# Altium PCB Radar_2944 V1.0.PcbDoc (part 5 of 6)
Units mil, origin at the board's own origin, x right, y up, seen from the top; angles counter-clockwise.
Board outline 3544.83 x 2556.65 mil, 8 copper layers (Top Layer, GND1, SIG1, PWR1, PWR2, SIG2, GND2, Bottom Layer), stack 55.2 mil thick; 301 components, 253 nets, 1055 pads, 1340 vias.
Unrouted connection lines stored in the file: 12.
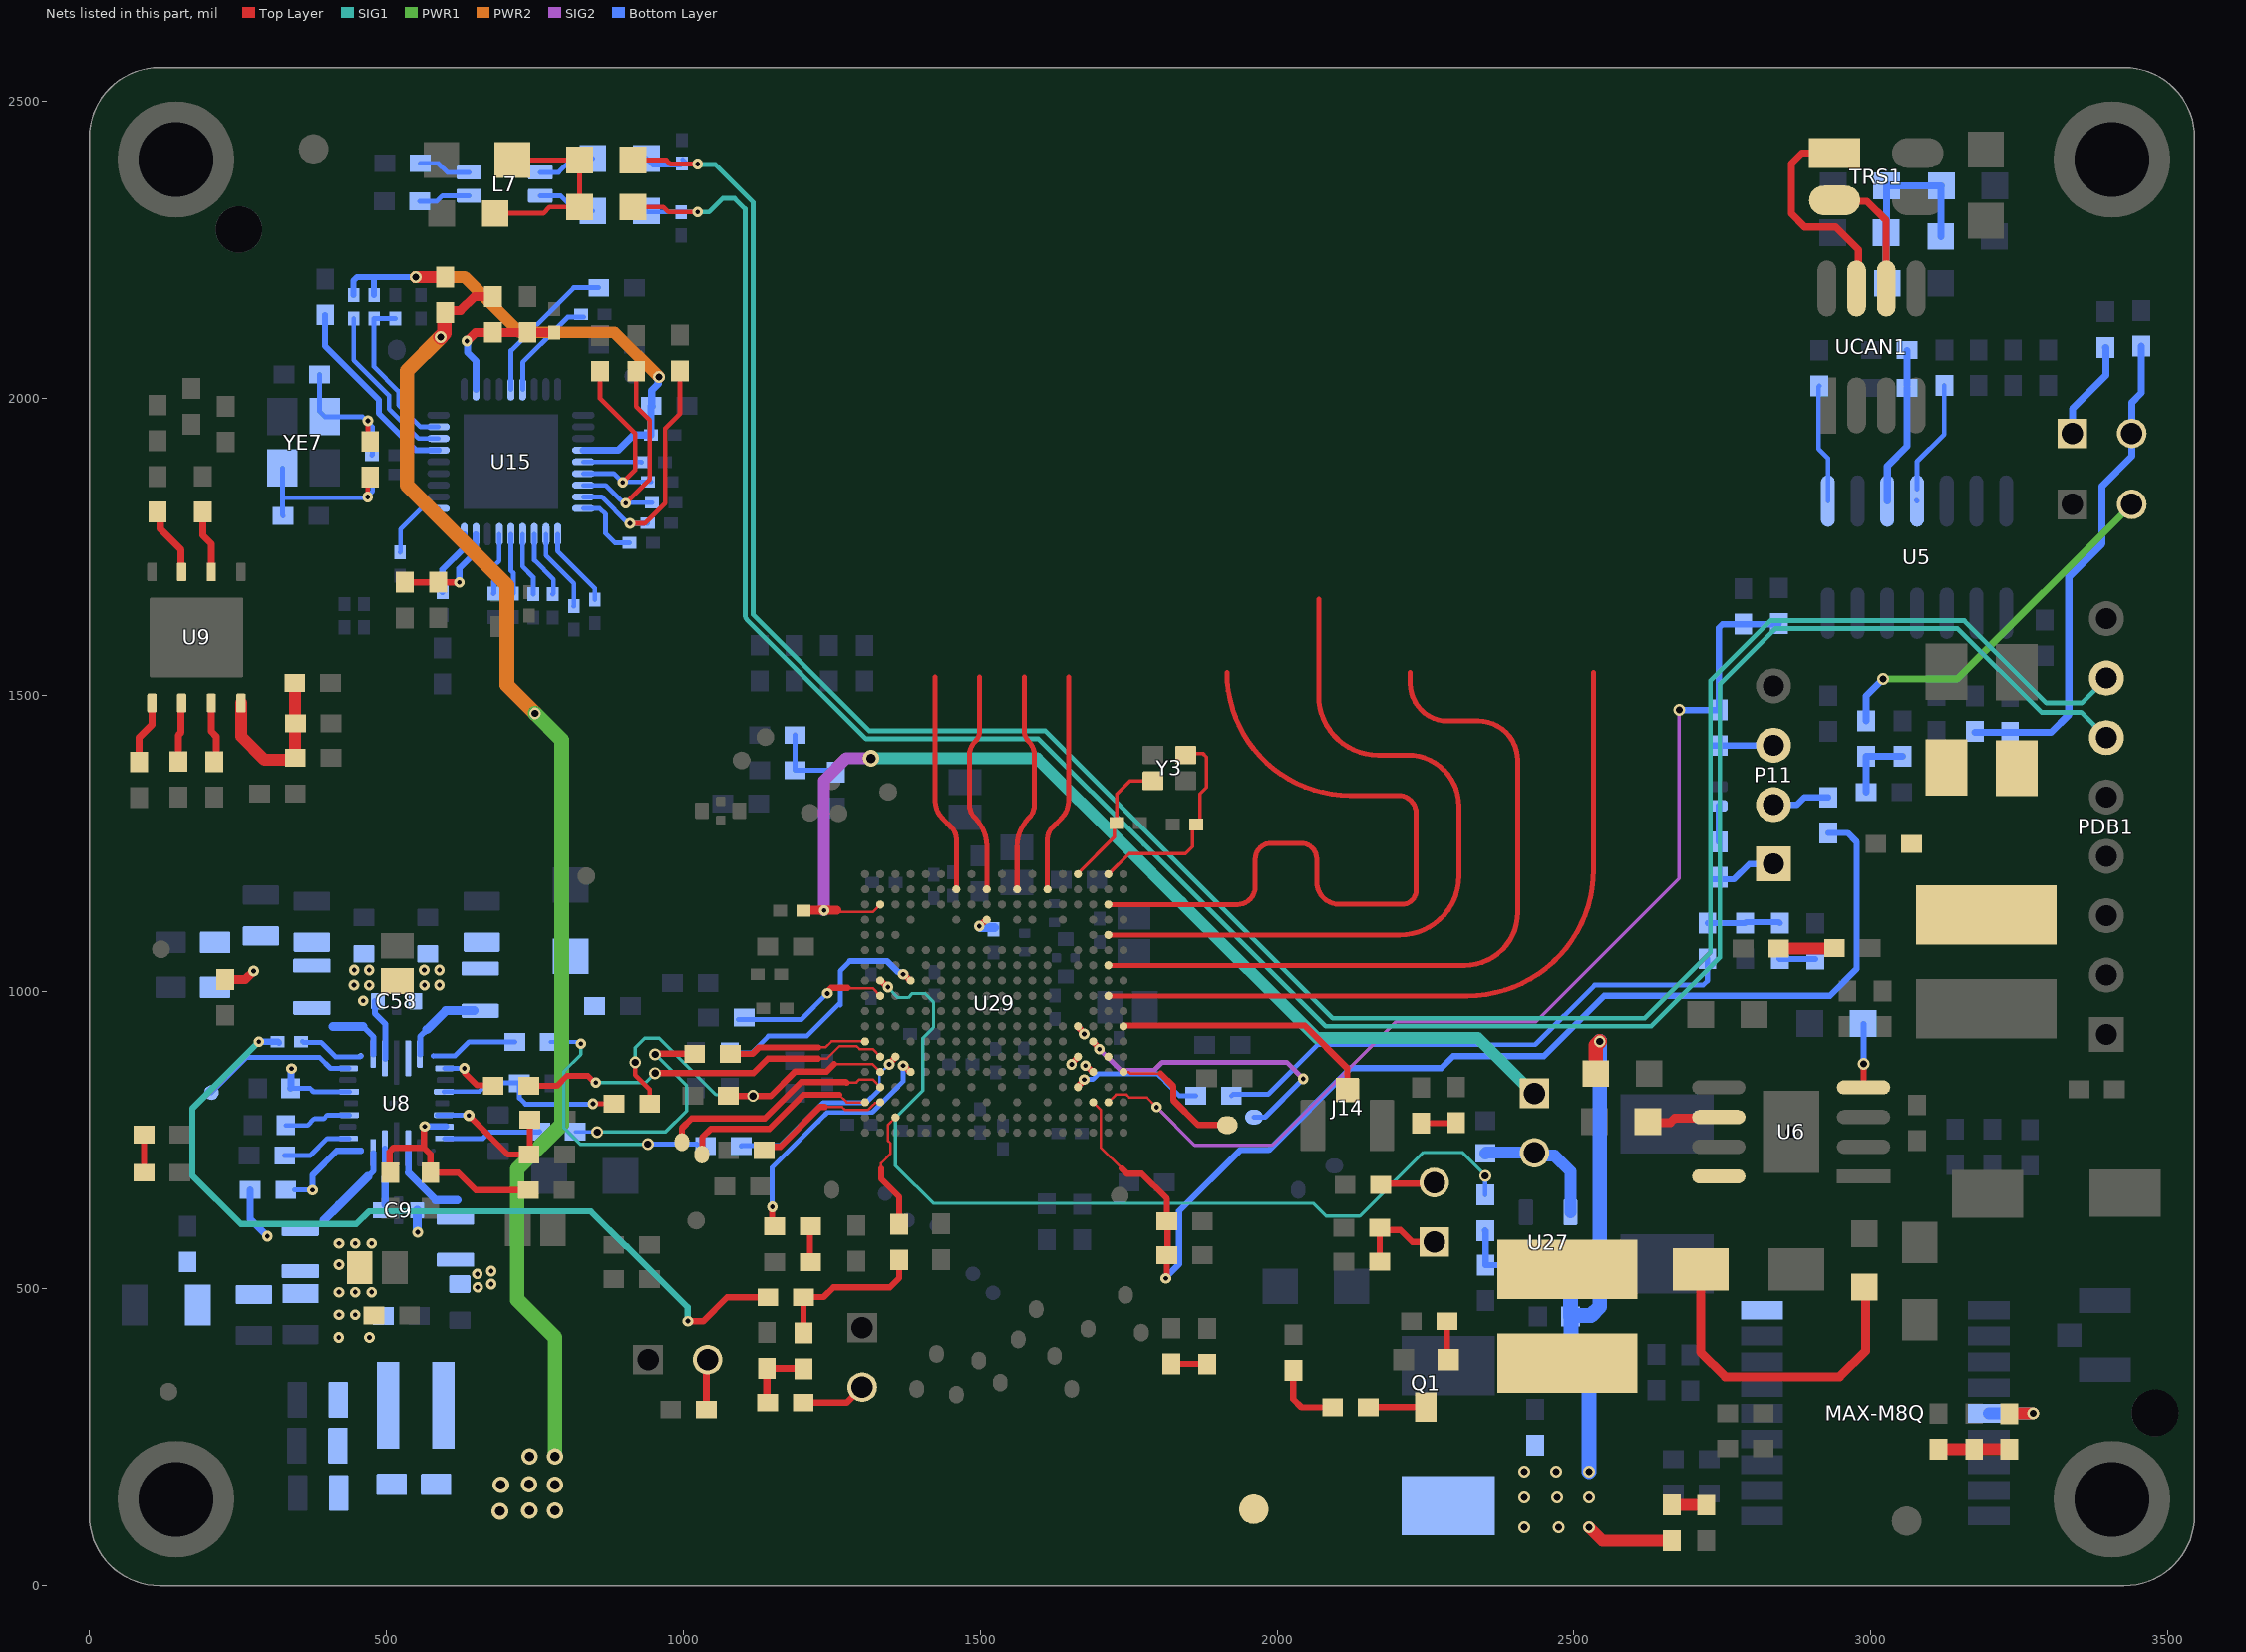
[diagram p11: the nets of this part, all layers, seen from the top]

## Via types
v1: diameter 13.77, hole 5.9, Top Layer to GND1, tented both sides, 427 vias
v2: diameter 18, hole 8, Top Layer to Bottom Layer, tented both sides, 341 vias
v3: diameter 13.77/13.77 (per signal layer), hole 5.9, Top Layer to GND1, tented both sides, 229 vias
v4: diameter 20, hole 12, Top Layer to Bottom Layer, tented both sides, 165 vias
v5: diameter 13.77, hole 5.9, Top Layer to GND1, tented top, 140 vias
v6: diameter 20, hole 10, Top Layer to Bottom Layer, tented both sides, 19 vias
v7: diameter 32, hole 20, Top Layer to Bottom Layer, tented both sides, 9 vias
v8: diameter 28, hole 16, Top Layer to Bottom Layer, tented both sides, 9 vias
v9: diameter 19.68, hole 7.87, Top Layer to Bottom Layer, tented both sides, 1 vias

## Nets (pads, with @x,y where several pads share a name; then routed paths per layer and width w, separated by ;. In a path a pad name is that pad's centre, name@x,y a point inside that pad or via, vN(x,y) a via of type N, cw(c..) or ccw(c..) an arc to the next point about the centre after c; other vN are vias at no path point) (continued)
MSS_SPIA_MOSI: pad.25 U29.U15 | length 398.5
  Top Layer w4.19: 1274.57,847.58 1291.61,847.58 1296.72,852.7 1311.52,852.7 ; 1311.53,852.69 1319.03,852.69 U29.U15@1331.81,839.9
  Top Layer w10.6: pad.25@997.69,747.06 997.69,770.72 1013.85,786.88 1137.54,786.88 1198.95,848.3 1273.85,848.3 1274.57,847.58 1275.16,846.99
MSS_SPIB_CLK: R63.2 R380.1 | length 454.6
  SIG1 w5.5: v2(827.69,912.93) 827.69,894.76 799.32,866.39 799.32,770.98 826.68,743.62 v4(940.29,743.62)
  Bottom Layer w6: R63.2@776.37,915.88 824.75,915.88 v2(827.69,912.93)
  Bottom Layer w8.3: v4(940.29,743.62) 1023.24,743.62 1031.23,735.63 R380.1@1032.53,736.93
MSS_SPIB_CS0: R190.1 R273.1 U29.U14 | length 634.6
  Top Layer w4.19: 1254.14,878.3 1265.26,878.3 ; 1265.28,878.29 1319.01,878.29 U29.U14@1331.81,865.5
  Top Layer w8: v4(919.16,881.74) 919.16,860.29 943.45,836.01 R190.1@943.45,811.76
  Top Layer w10.6: R273.1@1078.75,823.13 1080.24,823.13 1078.4,824.97 v4(1117.31,824.97) 1147.25,824.97 1188.18,865.9 1241.73,865.9 1254.14,878.3
  SIG1 w5.5: v4(919.16,881.74) 919.16,906.37 935.09,922.3 959.44,922.3 1054.63,827.11 1115.17,827.11 v4(1117.31,824.97)
MSS_SPIB_CS1: pad.26 U29.V16 | length 338.4
  Top Layer w4.19: 1262.43,827.1 1275.21,814.31 U29.V16@1306.22,814.31
  Top Layer w10.6: pad.26@1031.19,726.29 1032.02,727.12 1032.02,754.95 1046.34,769.28 1144.83,769.28 1202.64,827.1 1262.43,827.1
MSS_SPIB_MISO: R193.2 U29.U13 | length 636.4
  Top Layer w4: 1227.35,887.98 1242.24,887.98 1263.35,909.09 1291.57,909.09 1296.78,903.88 1319.01,903.88 U29.U13@1331.81,891.09
  Top Layer w10: R193.2@740.06,841.75 787.25,841.75 804.31,858.81 839.53,858.81 850.77,847.57 v2(852.94,847.57)
  Top Layer w10.6: v4(952.72,863.34) 1117.96,863.34 1142.6,887.98 1227.35,887.98
  SIG1 w5.5: v2(852.94,847.57) 936.95,847.57 v4(952.72,863.34)
MSS_SPIB_MOSI: R186.2 R381.1 | length 387
  Top Layer w10.6: v4(952.72,895.18) 953.64,896.11 1018.88,896.11 R381.1@1019.22,895.77
  SIG1 w6: v4(855.35,763.75) 855.86,764.26 970.07,764.26 1005.52,799.7 1005.52,842.38 v4(952.72,895.18)
  Bottom Layer w6: R186.2@818.22,764.75 854.36,764.75 v4(855.35,763.75)
MSS_UARTA_RX: RC31.1 Rs301.1 Rs303.2 U29.B16 | length 1780.4
  Top Layer w4.19: U29.B16@1715.67,814.31 1728.45,827.1 1735.94,827.1 ; 1735.96,827.11 1746.56,827.11 1751.36,822.31 1780.88,822.31 v2(1797,806.18)
  SIG2 w5.5: v2(1797,806.18) 1861.21,741.98 1992.24,741.98 2200.25,949.99 2435.82,949.99 2676.9,1191.07 v4(2676.9,1474.68)
  Bottom Layer w10.6: v4(2676.9,1474.68) 2743.32,1474.68 2743.64,1475 2743.64,1612.79 2749.85,1619 Rs303.2@2785,1619 2844,1619 Rs301.1@2845,1620
NERR_MCU: R76.2 U8.16 | length 119.6
  Bottom Layer w8.3: R76.2@329.09,724.53 372.01,724.53 400.76,753.29 U8.16@436.82,753.29
NetC8G_1: C8G.1 L11.1 R8G.2 | length 118.9
  Top Layer w20: C8G.1@3113.7,230.33 L11.1@3173.64,230.33 3173.92,230.06 R8G.2@3232.49,230.06
NetC11_2: C11.2 R16.1 U5.3 | length 262.7
  Bottom Layer w12: U5.3@3027.45,1826.48 3027.45,1885.48 3060.59,1918.62 R16.1@3060.59,2017.08 ; R16.1@3060.54,2021.25 C11.2@3060.54,2079.61
NetC13_2: C13.2 R15.1 R24.2 | length 121.3
  Bottom Layer w12: C13.2@2991.85,1336.34 2991.99,1336.48 R15.1@2991.99,1396.59 R24.2@3052.99,1396.59
NetC51_1: C51.1 C52.1 R5.2 U15.11 | length 240.7
  Top Layer w15: v2(635.63,2095.85) 650.3,2110.52 R5.2@679.46,2110.52 C51.1@737.88,2110.52 C52.1@782.71,2110.52
  Bottom Layer w12: v2(635.63,2095.85) 636.77,2094.7 636.77,2076.42 650.9,2062.3 U15.11@650.9,2014.6
NetC90_2: C90.2 C91.2 R37.2 U9.8 | length 281.5
  Top Layer w20: U9.8@255.44,1486.42 255.44,1430.6 295.18,1390.86 C91.2@340.38,1390.86 ; R37.2@346.65,1518.46 346.65,1452.2 346.65,1399.2 346.8,1399.04 C91.2@346.8,1394.2
NetC95_1: C95.1 R242.2 R248.1 YE7.1 | length 247.9
  Top Layer w8: v2(468.89,1961.79) 468.89,1930.66 R248.1@472.64,1926.91
  Bottom Layer w8: C95.1@387.71,2039.65 387.71,1977 396.27,1968.45 459.53,1968.45 466.19,1961.79 v2(468.89,1961.79) 468.89,1959.64 476.43,1952.1 476.43,1904.56 R242.2@475.7,1903.84
NetC121_1: C121.1 R246.1 R248.2 YE7.2 | length 302.9
  Top Layer w8: v2(468.62,1833.31) 468.62,1862.9 R248.2@472.64,1866.91
  Bottom Layer w8: YE7.2@325.25,1881.99 325.25,1832.03 ; C121.1@326.35,1801.51 325.25,1802.61 325.25,1832.03 ; R246.1@475.6,1871.45 476.88,1870.16 476.88,1843 468.59,1834.7 468.59,1832.03 325.25,1832.03
NetC123_2: C123.2 U8.18 | length 114.2
  Bottom Layer w8: C123.2@330.78,775.43 367.57,775.43 378.24,786.1 379.23,786.1 379.59,786.46 394.58,786.46 400.77,792.66 409.01,792.66
  Bottom Layer w8.3: 409.01,792.66 U8.18@437.8,792.66
NetC128_1: C128.1 J1.2 R52.1 R55.2 | length 841.2
  Bottom Layer w12: R52.1@3175.02,1437.12 3233.95,1437.12 3303.14,1437.12 3333.08,1467.05 3333.08,1698.51 3388.63,1754.07 3388.63,1851.42 3439.05,1901.84 J1.2@3439.05,1940.42 3439.05,1992.35 3455.11,2008.41 C128.1@3455.11,2087.27
NetC149_2: C149.2 P1.2 U27.5 | length 225.3
  Bottom Layer w20: C149.2@2350.97,728.2 2352.02,729.25 P1.2@2433.39,729.25 2438.18,724.47 2467.34,724.47 2493.85,697.96 U27.5@2493.85,628.94
NetC167_1: C167.1 R275.1 R281.1 R282.2 | length 339.1
  Top Layer w8: R282.2@683.31,2310.74 764.61,2310.74 775.19,2321.31 R281.1@825.64,2321.31 R275.1@825.64,2400.56 712.66,2400.56 C167.1@712.54,2400.68
NetCN1_1: CN1.1 RCN1.1 RCN2.2 RCN3.1 RCN5.2 | length 345.8
  Bottom Layer w12: CN1.1@3026.4,2277.07 CN1.1@3025.64,2277.83 3025.64,2194.57 RCN1.1@3027.45,2192.77 ; CN1.1@3026.39,2277.9 RCN3.1@3026.39,2356.76 ; RCN3.1@3026.39,2359.78 RCN3.1@3026.39,2356.76 ; RCN2.2@3117.45,2271.76 RCN5.2@3117.45,2356.76 ; RCN5.2@3118.45,2356.76 RCN5.2@3117.45,2356.76 ; RCN3.1@3026.39,2356.76 RCN5.2@3117.45,2356.76
NetCu6_1: Cu6.1 Dr8.K Dr9.K L4.1
NetD4_1: D4.1 RC33.1 | length 60.7
  Bottom Layer w10: RC33.1@2743.51,1252.68 D4.1@2743.51,1313.36
NetD6_1: D6.1 R347.1 | length 59.8
  Top Layer w10: R347.1@2242.09,779.19 2300.84,779.19 D6.1@2301.61,779.97
NetD12_1: D12.1 R331.1 | length 60.8
  Top Layer w10.6: D12.1@1821.7,373.66 1881.94,373.66 R331.1@1882.33,373.28
NetD13_1: D13.1 R263.1 | length 120.2
  Top Layer w10.6: R263.1@2027.33,362.8 2027.33,314.31 2040.89,300.76 D13.1@2093.45,300.76
NetD13_2: D13.2 Q1.3 | length 96.7
  Top Layer w10.6: D13.2@2153.45,300.76 2153.78,301.09 Q1.3@2249.97,301.09
NetD14_1: D14.1 R332.1 | length 94.4
  Top Layer w20: D14.1@2844.45,1072.76 2844.8,1073.11 2937.8,1073.11 R332.1@2938.45,1073.76
NetD16_1: D16.1 R103.1 | length 58
  Top Layer w5.5: D16.1@2722.32,135.98 D16.1@2722.45,135.85
  Top Layer w20: R103.1@2664.49,135.98 D16.1@2722.32,135.98
NetDS2_1: DS2.1 R262.1 | length 64.1
  Top Layer w10: R262.1@92.34,695.6 DS2.1@92.34,759.66
NetJ1_1: J1.1 R110.2 | length 170
  Bottom Layer w12: J1.1@3339.05,1938.97 J1.1@3339.05,1940.42 3339.05,1982.04 3395.47,2038.45 3395.47,2084.49 R110.2@3394.68,2085.28
NetJ10_1: J10.1 R334.1 R335.2 | length 159
  Top Layer w10.6: R335.2@2172.45,545.76 2172.6,545.91 2172.6,598.83 2172.6,602.6 R334.1@2172.45,602.76 2176.38,598.83 2207.76,598.83 2227.54,579.04 J10.1@2264.47,579.04
NetJ10_2: J10.2 R333.1 | length 93
  Top Layer w10.6: R333.1@2174.2,672.54 2178.79,677.13 2262.56,677.13 J10.2@2264.47,679.04
NetJ11_2: J11.2 R267.2 | length 84.8
  Top Layer w12: R267.2@1038.72,296.92 1038.72,378.74 J11.2@1040.82,380.84
NetL1_1: L1.1 U8.11 | length 142.1
  Bottom Layer w11: 537.4,695.5 U8.11@537.4,736.37
  Bottom Layer w12: 537.4,695.5 583.41,649.48
  Bottom Layer w15: 583.41,649.48 619.59,649.48
NetMAX-M8Q_14: MAX-M8Q.14 R8G.1 | length 120.4
  Top Layer w20: R8G.1@3229,286.93 3232.76,290.69 v4(3273.06,290.69)
  Bottom Layer w20: MAX-M8Q.14@3198.28,290.69 v4(3273.06,290.69)
NetP11_1: P11.1 RC33.2 | length 113.5
  Bottom Layer w10.6: RC33.2@2733.16,1189.48 2769.22,1189.48 2795.1,1215.36 P11.1@2835.92,1215.36
NetP11_2: P11.2 RC32.2 | length 97.4
  Bottom Layer w10.6: P11.2@2835.92,1315.36 2836.14,1315.13 2875.14,1315.13 2887.7,1327.69 RC32.2@2928.04,1327.69
NetP11_3: P11.3 RC31.2 | length 100.6
  Bottom Layer w10.6: RC31.2@2735.35,1414.88 P11.3@2835.92,1414.88
NetPL1_2: PL1.2 R15.2 | length 622.4
  PWR1 w12: v4(3020.58,1526.94) 3145.16,1526.94 PL1.2@3439.05,1820.83
  Bottom Layer w12: R15.2@2991.99,1456.59 2991.99,1498.35 v4(3020.58,1526.94)
NetQ1_1: Q1.1 R266.2 | length 65.3
  Top Layer w10.6: R266.2@2285.96,445.59 2285.96,383.11 Q1.1@2287.97,381.09
NetR1_1: R1.1 R79.2 U15.35 | length 184.9
  Top Layer w10.6: R79.2@530.92,1689.53 587.36,1689.53 R1.1@587.52,1689.69 587.92,1689.3 v2(622.83,1689.3)
  Bottom Layer w10.6: v2(622.83,1689.3) 622.83,1712.64 650.9,1740.71 U15.35@650.9,1770.41
NetR3_2: R3.2 U29.U9 | length 265.4
  Top Layer w4.19: 1276.68,1006.24 1319.01,1006.24 U29.U9@1331.81,993.45
  Top Layer w10.6: v2@1242.6,1000.53 1249.22,1007.15 1276.68,1007.15
  Bottom Layer w8.3: R3.2@1092.68,953.62 1198.69,953.62 v2(1242.6,997.53)
NetR21_2: R21.2 U5.1 | length 200.9
  Bottom Layer w8: R21.2@2912.77,2020.32 2911.58,2019.13 2911.58,1914.36 2927.45,1898.49 U5.1@2927.45,1826.48
NetR25_2: R25.2 U5.4 | length 195.1
  Bottom Layer w8: U5.4@3076.67,1827.26 U5.4@3077.45,1826.48 ; U5.4@3077.45,1846.11 3077.45,1893.3 3123.11,1938.97 3123.11,2020.83 R25.2@3123.36,2021.08
NetR31_2: R31.2 U29.R8 | length 431.5
  Top Layer w10.6: v2(1370.2,1029.69) 1377.97,1023.22 U29.R8@1382.99,1019.04
  Bottom Layer w8.3: R31.2@1067.3,897.9 1115.42,897.9 1143.21,925.69 1208.22,925.69 1227.35,944.82 1264.24,981.71 ; 1281.08,1051.93 1264.24,1035.1 1264.24,981.71 ; 1264.24,981.71 1264.24,978.38 1264.45,978.18 1264.45,981.92 1264.24,981.71
  Bottom Layer w10.6: 1281.08,1051.93 1342.87,1051.93 1361.41,1033.39 1364.49,1033.39 1368.19,1029.69 v2(1370.2,1029.69)
NetR50_1: R50.1 R350.1 U15.8 | length 280.7
  Bottom Layer w8: R350.1@515.07,2133.67 R50.1@479.23,2133.67 479.23,2052.75 520.86,2011.12 520.86,1988.24 557.54,1951.56 U15.8@587.86,1951.56
NetR51_1: R51.1 U15.7 | length 280.7
  Bottom Layer w8: R51.1@444.95,2133.67 444.95,2063.98 504.56,2004.37 504.56,1981.49 554.18,1931.88 U15.7@587.86,1931.88
NetR63_1: R63.1 U8.1 | length 147
  Bottom Layer w8.3: U8.1@579.04,892.43 615.53,892.43 638.97,915.88 R63.1@716.37,915.88
NetR74_2: R74.2 U15.28 | length 135.9
  Bottom Layer w8: U15.28@788.7,1770.41 788.7,1742.17 833.88,1696.98 851.27,1679.59 851.27,1660.51 R74.2@851.32,1660.46
NetR89_1: R89.1 U15.6 | length 329.6
  Bottom Layer w10: R89.1@397.14,2139.99 397.14,2087.33 487.26,1997.2 487.26,1974.33 549.71,1911.88 587.55,1911.88 U15.6@587.86,1912.19
NetR96_2: R96.2 U15.33 | length 104.1
  Bottom Layer w8: R96.2@680.42,1670.39 681.27,1671.24 681.27,1716.67 690.27,1725.67 U15.33@690.27,1770.41
NetR100_2: R100.2 U15.32 | length 102
  Bottom Layer w8: U15.32@709.96,1770.41 709.96,1708.93 714.02,1704.87 714.02,1670.99 R100.2@713.42,1670.39
NetR156_1: R156.1 R172.2 R316.2 | length 128.3
  Bottom Layer w8.3: R172.2@1188.42,1432.58 1188.51,1432.49 R316.2@1188.51,1373.6 1254.53,1373.6 R156.1@1256.84,1371.29
NetR159_2: R159.2 R409.1 U27.3 | length 134.3
  Bottom Layer w10.6: R159.2@2350.32,598.05 2350.98,597.38 R409.1@2350.98,540.04 2380.54,540.04 2394.36,526.22 U27.3@2421.27,526.22
NetR178_2: R178.2 U15.31 | length 108.1
  Bottom Layer w8: U15.31@729.64,1770.41 729.64,1715.98 747.49,1698.12 747.49,1690.84 747.49,1687.95 747.49,1669.84 R178.2@747.42,1669.76
NetR186_1: R186.1 U8.8 | length 164.7
  Bottom Layer w8.3: U8.8@598.23,753.29 662.92,753.29 673.62,763.99 757.46,763.99 R186.1@758.22,764.75
NetR190_2: R190.2 R292.2 U8.4 | length 329.7
  Top Layer w8.3: v2(848.12,811.94) 889.08,811.94 889.7,811.32 R190.2@890.35,811.97
  Bottom Layer w8.3: U8.4@597.25,832.03 597.59,832.37 656.6,832.37 671.35,847.12 723.42,847.12 R292.2@724.35,846.19 724.35,821.22 734.41,811.16 841.88,811.16 842.66,811.94 v2(848.12,811.94)
NetR193_1: R193.1 U8.2 | length 94.2
  Top Layer w10.6: v2(631.42,871.58) 632.83,870.17 632.83,862.81 652.87,842.77 679.03,842.77 R193.1@680.06,841.75
  Bottom Layer w8.3: U8.2@598.23,871.4 626.72,871.4 v2@627.02,871.1
NetR225_2: R225.2 U15.30 | length 114.6
  Bottom Layer w8: U15.30@749.33,1770.41 749.33,1726.8 781.68,1694.44 781.68,1671.02 R225.2@780.42,1669.76
NetR230_2: R230.2 U15.29 | length 141
  Bottom Layer w8: U15.29@769.01,1770.41 769.01,1734.66 816.16,1687.5 816.16,1649.51 R230.2@815.77,1649.11
NetR234_2: R234.2 U15.27 | length 120.3
  Bottom Layer w8: U15.27@832.05,1813.77 859.6,1813.77 869.32,1804.05 869.32,1771.86 885,1756.18 R234.2@909.69,1756.18
NetR247_2: R247.2 U15.36 | length 112.2
  Bottom Layer w10.6: R247.2@594.68,1673.37 594.68,1711.22 630.98,1747.52 630.98,1770.18 U15.36@631.22,1770.41
NetR249_2: R249.2 U15.1 | length 117.6
  Bottom Layer w8: R249.2@523.28,1740.18 523.94,1740.85 523.94,1779.24 558.24,1813.54 587.63,1813.54 U15.1@587.86,1813.77
NetR380_2: R380.2 U29.T13 | length 338.2
  Top Layer w10.6: v2(1346.75,878.29) 1353.22,886.07 U29.T13@1357.4,891.09
  Bottom Layer w4: 1328.58,834.01 1330.61,836.03 1330.61,862.15 v2(1346.75,878.29)
  Bottom Layer w8.3: R380.2@1097.45,740.76 1098.37,741.68 1163.58,741.68 1227.35,805.44 1235.64,813.73 1308.31,813.73 1328.58,834.01
NetR381_2: R381.2 U29.V12 | length 221.3
  Top Layer w4.19: 1227.35,906.7 1239.5,906.7 1249.88,917.08 1305.81,917.08 U29.V12@1306.22,916.68
  Top Layer w10.6: R381.2@1093.94,895.77 1116.44,895.77 1127.37,906.7 1227.35,906.7
NetR386_2: R386.2 U29.D15 | length 224.4
  Top Layer w10.6: U29.D15@1664.49,839.9 1668.67,844.92 v2(1675.14,852.7)
  Bottom Layer w8.3: v2(1675.14,852.7) 1689.52,852.7 1699.06,862.23 1799.14,862.23 1812.95,848.42 1812.95,847.68 1823,837.63 1835.66,824.97 1838.58,824.97 R386.2@1863.03,824.97
NetR392_2: R392.2 U29.U16 | length 233.1
  Top Layer w4.19: 1238.68,806.22 1267.57,806.22 1272.28,801.52 1311.52,801.52 1319.01,809.01 1322.93,812.94 1330.44,812.94 U29.U16@1331.81,814.31
  Top Layer w10.6: R392.2@1136.13,733.32 1142.21,739.4 1163.32,739.4 1230.15,806.22 1238.68,806.22
NetRCN11_2: RCN11.2 RCN14.1 RCN19.2 | length 120.3
  Top Layer w12: RCN14.1@1142.01,308.76 1140.74,310.03 RCN19.2@1140.74,366.35 1201.82,366.35 RCN11.2@1202.56,365.61
NetRCN12_2: RCN12.2 RCN18.2 | length 65
  Top Layer w8.3: RCN18.2@1212.18,546.69 RCN18.2@1214.01,544.86
  Top Layer w10: RCN18.2@1207.84,543.26 RCN18.2@1212.18,543.26 ; RCN18.2@1213.61,540.35 1213.61,546.69 RCN12.2@1213.61,598.4
NetRCN13_2: RCN13.2 RCN15.1 RCN17.2 | length 123.5
  Bottom Layer w10: RCN13.2@2724.52,1115.75 RCN17.2@2788.1,1115.75 2789.91,1117.55 2844.65,1117.55 RCN15.1@2846.47,1115.73
NetRCN15_2: RCN15.2 RCN25.1 | length 60
  Bottom Layer w10.6: RCN15.2@2846.47,1055.73 2847.07,1055.14 RCN25.1@2906.19,1055.14
NetTP8_1: TP8.1 U8.22 | length 263.1
  Bottom Layer w8.3: TP8.1@205.67,830.62 264.67,889.62 387.79,889.62 406.02,871.4 U8.22@436.82,871.4
NetTRS1_1: TRS1.1 UCAN1.7 | length 370.6
  Top Layer w12: TRS1.1@2938.86,2412.57 2883.53,2412.57 2865.77,2394.8 2865.77,2310.35 2888.31,2287.81 2940.72,2287.81 2978.86,2249.67 UCAN1.7@2978.86,2182.16
NetTRS1_2: TRS1.2 UCAN1.6 | length 233.1
  Top Layer w12: TRS1.2@2920.35,2331.09 2993.26,2331.09 3025.7,2298.64 UCAN1.6@3025.7,2184.31
NRSTOUT: R99.2 R102.1 U8.6 | length 241.9
  Top Layer w10: v9(638.77,792.05) 704.54,726.29 R99.2@740.58,726.29 741.64,727.34 R102.1@741.64,785.1
  Bottom Layer w8.3: U8.6@585.44,792.66 597.25,792.66 638.17,792.66 v9(638.77,792.05)
OSC_CLKTOP: J14.1 U29.A11 | length 442.8
  Top Layer w10.6: U29.A11@1741.26,942.27 1741.87,942.88 1744.11,942.88 1744.79,943.55 1838.58,943.55 2046.13,943.55 2118.21,871.46 J14.1@2118.21,836.05
PMIC_CLK: R75.1 RCN24.2 | length 1427.5
  Top Layer w10.6: v2(1007.62,445.71) 1033.76,445.71 1073.91,485.87 RCN24.2@1142.56,485.87
  SIG1 w10.6: v2(285.67,916.28) 173.52,804.13 173.52,690.58 255.13,608.97 449.14,608.97 470.57,630.41 844.83,630.41 903.62,571.61 905.27,571.61 1007.62,469.26 v2(1007.62,445.71)
  Bottom Layer w8.3: R75.1@319.56,914.52 R75.1@319.56,916.56
  Bottom Layer w10.6: v2(285.67,916.28) R75.1@316.89,916.28 317.79,916.28 R75.1@319.56,914.52
PMIC_CLK_OUT: R218.1 U29.T17 | length 206.6
  Top Layer w4.19: 1333.23,702.68 1333.23,711.49 1349.31,727.58 1349.31,745.07 1344.62,749.76 1344.62,756.97 1344.61,775.93 U29.T17@1357.4,788.72
  Top Layer w10.5: 1333.23,702.68 1333.23,685.23 1363.82,654.64 R218.1@1363.82,608.71
PMIC_EN: R125.1 U8.15 | length 153.8
  Bottom Layer w8.3: R125.1@345.6,666.39 v2(375.86,666.39)
  Bottom Layer w10.6: v2(375.86,666.39) 375.86,691.6 416.69,732.43 U8.15@457.3,732.43
PMIC_NINT: R17.2 R106.1 R210.1 U8.7 | length 392.4
  Top Layer w10.6: R210.1@505.55,695.09 505.55,731.09 511.76,737.3 563.6,737.3 ; v2@563.6,773.73 563.6,737.3 ; R106.1@739.35,666.13 650.51,666.13 621.04,695.6 R17.2@574.32,695.6 574.32,726.58 563.6,737.3
  Bottom Layer w10.6: v2(564.67,773.73) v2@569.18,773.73 ; v2@569.15,773.7 600.24,773.7 U8.7@600.49,773.96
PMICOUT_1V0: C132.1 C134.1 L8.2 R71.2 R73.1 R111.1 | length 53.9
  Top Layer w15: R71.2@228.67,1020.87 262.64,1020.87 v2(276.76,1034.99)
PMICOUT_1V2: C129.1 C130.1 L2.2 R30.1 R291.2
PMICOUT_1V8: C125.1 L9.2 R14.2 R104.1
PMIN3V3: C3.2 C6.2 C7.1 C8.2 C9.1 C9.3 C31.1 C58.1 C58.3 C143.1 C144.2 C153.2 C199.1 C200.1 C201.1 C202.1 L1.2 L10.2 R125.2 R200.2 U8.13 U8.20 U8.25 U8.27 | length 462.5
  Bottom Layer w8.3: C3.2@338.82,838.07 371.46,838.07 377.51,832.03 U8.20@437.8,832.03
  Bottom Layer w10: C58.3@480.41,984.66 480.41,964.08 498.16,946.32 498.16,887.29 U8.25@497.96,887.09 ; U8.13@497.84,736.55 497.84,688.77 497.97,688.64
  Bottom Layer w12: R125.2@270.92,666.39 270.92,617.58 v2(299.84,588.66) ; C3.2@338.82,838.07 339.62,838.88 339.62,870.05 v2(340.42,870.86) ; C9.3@497.97,641.24 497.97,688.64
  Bottom Layer w15: C9.1@551.92,632.2 551.92,596.9 552.87,595.94 v2(552.87,595.13)
  other v2: 419.81,418.4 471.35,418.4 420.09,456.39 447.6,456.39 420.1,494.39 447.6,494.39 475.1,494.39 653.79,502.39 676.76,508.06 653.33,525 676.76,529.92 420.1,540.75 420.1,576.55 447.6,576.55 475.1,576.55 460.91,985.15 445.58,1011.51 470.95,1011.38 564.1,1011.38 589.47,1011.5 471.07,1036.75 563.98,1036.75 445.7,1036.87 589.35,1036.87
QSPI_D0_FLASH: R61.1 U9.5 | length 107.9
  Top Layer w12: R61.1@83.55,1387.6 83.55,1428.28 105.44,1450.17 U9.5@105.44,1486.42
QSPI_D1_FLASH: R46.2 U9.2 | length 102.1
  Top Layer w12: R46.2@191.37,1803.18 191.37,1768.43 205.44,1754.36 U9.2@205.44,1706.9
QSPI_D2_FLASH: R48.2 U9.3 | length 117.7
  Top Layer w12: R48.2@114.8,1807.8 119.41,1803.18 119.41,1779.33 154.49,1744.24 154.49,1707.85 U9.3@155.44,1706.9
QSPI_D3_FLASH: R49.1 U9.7 | length 102.2
  Top Layer w12: U9.7@205.44,1486.42 205.44,1438.68 213.52,1430.6 R49.1@213.52,1387.6
QSPI_SCLK_FLASH: R47.1 U9.6 | length 101.2
  Top Layer w12: R47.1@149.79,1387.6 149.79,1432.36 154.5,1437.07 154.5,1485.48 U9.6@155.44,1486.42
REG3.3V: C145.1 CP8.1 Cu2.1 FB1.1 L3.2 L10.1 pad.38@1960.71,128.74 R5.1 R56.2 R103.2 R200.1 U27.1 | length 3264.2
  Top Layer w15: FB1.1@597.84,2142.68 FB1.1@598.8,2143.64 602.34,2147.18 624.99,2147.18 648.33,2170.52 R5.1@679.46,2170.52
  Top Layer w20: v4(2524.98,98.73) 2547.72,75.98 R103.2@2664.49,75.98
  Top Layer w25: v4(591.47,2102.52) 597.84,2108.89 FB1.1@597.84,2142.68 ; R56.2@2536.45,862.76 2536.45,909.93 v4(2543.19,916.68)
  PWR1 w25: v4(750.55,1469.28) 795.58,1424.25 795.58,776.51 720.35,701.28 720.35,481.86 784.03,418.18 v8(784.03,218.17)
  PWR2 w25: v4(591.47,2102.52) 534.75,2045.8 534.75,1853.07 703.32,1684.5 703.32,1516.51 v4(750.55,1469.28)
  Bottom Layer w25: U27.1@2493.85,526.57 2494.12,526.31 2494.12,453.69 C145.1@2494.28,453.52 2495.12,452.69 2495.12,395.7 2524.98,365.84 v4(2524.98,192.38) ; C145.1@2494.28,454.51 2494.98,455.2 2528.55,455.2 2543.19,469.85 v4(2543.19,916.68)
  other v4: 2415.96,98.73 2473.8,98.73 2415.96,148.62 2471.6,148.62 2524.98,148.62 2415.96,192.38 2470.01,192.38
  other v8: 691.38,125.44 740.99,126.59 784.03,126.54 692.9,170.43 784.03,170.43 740.27,171.15 741.18,217.85
REG_3.3V: C40.1 C44.1 FB1.2 R50.2 R51.2 U15.22 | length 919.4
  Top Layer w20: v4(549.41,2203.64) FB1.2@598.8,2203.64
  PWR2 w20: v4(549.41,2203.64) 631.75,2203.64 724.7,2110.69 884.15,2110.69 v4(959.36,2035.48)
  Bottom Layer w10: R51.2@444.95,2173.04 444.95,2197.78 450.81,2203.64 479.23,2203.64 ; R50.2@479.23,2173.04 479.23,2203.64 ; v4(549.41,2203.64) 479.23,2203.64
  Bottom Layer w12: U15.22@832.05,1912.19 890.84,1912.19 916.41,1937.77 C44.1@945.93,1937.77 945.93,1983.92 C40.1@948.27,1986.26 ; C40.1@946.07,1986.7 946.9,1987.53 946.9,2012.67 957.83,2023.6 957.83,2033.95 v4(959.36,2035.48)
RESET_M8: MAX-M8Q.9
RT/CLK: R58.2 U6.4 | length 107.6
  Top Layer w10: U6.4@2987.58,839.38 v4(2987.58,878.86)
  Bottom Layer w8: R58.2@2986.93,946.76 R58.2@2987.58,946.1
  Bottom Layer w10: v4(2987.58,878.86) R58.2@2987.58,946.1
RX1: U29.M2 | length 369.3
  Top Layer w8.4: 1424.33,1530.09 1424.33,1321.23 ccw(c1465.12,1321.23) 1436.28,1292.39 1451.78,1276.89 cw(c1432.51,1257.61) 1459.76,1257.61 U29.M2@1459.76,1172.58
RX2: U29.K2 | length 369.9
  Top Layer w8.4: 1499.13,1530.09 1499.13,1440.14 cw(c1473.64,1440.14) 1491.67,1422.12 ccw(c1515.32,1398.47) 1481.87,1398.47 1481.87,1315.34 ccw(c1513.69,1315.34) 1491.19,1292.83 cw(c1443.5,1245.15) 1510.94,1245.15 U29.K2@1510.94,1172.58
RX3: U29.H2 | length 369.9
  Top Layer w8.4: U29.H2@1562.12,1172.58 1562.12,1245.15 cw(c1629.57,1245.15) 1581.88,1292.83 ccw(c1559.37,1315.34) 1591.2,1315.34 1591.2,1398.47 ccw(c1557.75,1398.47) 1581.4,1422.12 cw(c1599.42,1440.14) 1573.94,1440.14 1573.94,1530.09
RX4: U29.F2 | length 369.3
  Top Layer w8.4: U29.F2@1613.31,1172.58 1613.31,1257.61 cw(c1640.56,1257.61) 1621.29,1276.89 1636.79,1292.39 ccw(c1607.94,1321.23) 1648.74,1321.23 1648.74,1530.09
RX_D0: R237.2 R255.1 U15.26 | length 428
  Top Layer w8: v2(910.34,1788.58) 935.36,1788.58 969.58,1822.8 969.58,1948.89 994.45,1973.76 R255.1@994.45,2040.12
  Bottom Layer w8: U15.26@832.05,1833.45 862.96,1833.45 907.84,1788.58 v2(910.34,1788.58) 939.6,1788.58 R237.2@940.16,1789.15
RX_D1: R238.2 R256.1 U15.25 | length 377.4
  Top Layer w8: v2(903.48,1822.75) 943.71,1862.98 943.71,1962.77 920.95,1985.52 R256.1@920.95,2045.07
  Bottom Layer w8: U15.25@832.05,1853.14 869.44,1853.14 894.83,1827.75 895.77,1827.75 v2@900.7,1822.81 ; v2@899.97,1822.81 v2@900.7,1822.81 ; v2(903.48,1822.75) 900.77,1822.75 v2@900.7,1822.81 ; v2@903.48,1823.71 R238.2@947.68,1823.71
RX_D2: R239.2 R257.1 U15.24 | length 340.4
  Top Layer w8: R257.1@860.25,2045.07 860.25,1999.24 919.13,1940.37 919.13,1878.69 v2(898.26,1857.81)
  Bottom Layer w8: U15.24@832.05,1872.82 883.25,1872.82 v2(898.26,1857.81) ; v2@898.26,1858.71 R239.2@940.68,1858.71 R239.2@945.98,1858.71
RX_D3: R240.2 U15.23 | length 97.9
  Bottom Layer w8: U15.23@832.05,1892.51 832.25,1892.31 929.21,1892.31 R240.2@929.65,1891.87
RX_DV: R245.2 U15.15 | length 179.5
  Bottom Layer w8.3: U15.15@729.64,2014.6 729.64,2060.17 788.7,2119.22 805.76,2136.29 R245.2@832.06,2136.29
RX_ER: R253.1 U15.14 | length 256.9
  Bottom Layer w8.3: U15.14@709.96,2014.6 709.96,2079.67 815.71,2185.42 R253.1@857.96,2185.42
SL_ST: PSO1.2 RCN14.2 | length 110.2
  Top Layer w10.6: RCN14.2@1202.01,308.76 1275.45,308.76 PSO1.2@1301.45,334.76
SOP0_TDO: R386.1 RCN13.1 | length 918.7
  Bottom Layer w8.3: R386.1@1923.03,824.97 1925.69,827.62 1984.72,827.62 2068.42,911.32 2434.57,911.32 2534.57,1011.31 2717.07,1011.31 2724.52,1018.76
  Bottom Layer w10: 2724.52,1018.76 RCN13.1@2724.52,1055.75
SOP1_MSS_SPIB_CS2: RCN12.1 U29.R14 | length 429.8
  Top Layer w8.3: RCN12.1@1152.4,607.06 RCN12.1@1154.01,605.45
  Top Layer w10: v2(1149.96,637.95) 1149.96,604.62 RCN12.1@1152.4,607.06
  Top Layer w10.6: v2(1370.2,876.15) 1377.97,869.67 U29.R14@1382.99,865.5
  Bottom Layer w8.3: v2(1149.96,637.95) 1149.96,704.58 1227.35,781.97 1239.11,793.73 ccw(c1227.35,805.44) 1241.72,797.13 1318.38,797.13 1355.19,833.94 1355.19,834.21 1370.16,849.19 v2(1370.2,876.15) v2(1370.2,876.15)
SOP2_PMIC_CLK: R218.2 RCN11.1 RCN24.1 | length 265.4
  Top Layer w10: RCN11.1@1202.56,425.61 RCN24.1@1202.56,485.87 1236.48,485.87 1236.89,486.28
  Top Layer w10.5: 1236.89,486.28 1253,502.39 1348.01,502.39 1363.82,518.2 R218.2@1363.82,548.71
SOP3_MSS_UARTB_TX: pad.40 U29.A14 | length 225.8
  Top Layer w4.19: U29.A14@1741.26,865.5 1749.97,865.5 1753.09,862.38 1804.08,862.38
  Top Layer w10.6: 1804.08,862.38 1825.28,841.18 1825.28,817.73 1867.08,775.93 pad.40@1916.23,775.93
SOP4_MSS_UARTA_TX: R309.1 R312.2 RC32.1 U29.C16 | length 2060.7
  Top Layer w4.19: U29.C16@1690.08,814.31 1702.87,801.52 1702.87,738.31 1738.51,702.68
  Top Layer w10.6: 1738.51,702.68 1747.14,694.04 1772.07,694.04 1814.45,651.67 1814.45,619.76 1815.55,618.65 1815.55,562.86 R309.1@1814.45,561.76 ; v2(1812.73,517.81) 1814.45,519.52 R309.1@1814.45,545.8 ; R309.1@1815.13,545.8 R309.1@1815.13,561.76
  Bottom Layer w10.6: v2@1814.26,520.97 1834.8,541.5 1834.8,630.76 1937.72,733.68 1985.69,733.68 2123.87,871.86 2276.28,871.86 2296.59,892.17 2449.3,892.17 2550.69,993.56 2930.89,993.56 2975.95,1038.62 2975.95,1252.49 2960.74,1267.69 RC32.1@2928.04,1267.69
SS: C41.1 U6.6 | length 129.4
  Top Layer w15: C41.1@2618.01,779.97 2661.92,779.97 2669.6,787.65 2741.76,787.65 U6.6@2743.49,789.38
SW: C1.2 D8.K L3.1 U6.8 | length 568.5
  Top Layer w15: D8.K@2713.04,532.95 2713.04,393.53 2754.57,351.99 2947.26,351.99 2991.18,395.91 C1.2@2991.18,511.42
SW_B1: L9.1 U8.28 | length 139.3
  Bottom Layer w10: U8.28@557.01,894.47 557.01,925.5 568.14,936.62
  Bottom Layer w15: 568.14,936.62 600.2,968.69 L9.1@647.39,968.69
SW_B2: L8.1 U8.24 | length 105
  Bottom Layer w10: 460.91,941.89 478.27,924.53 U8.24@478.27,894.47
  Bottom Layer w15: 410.54,941.89 460.91,941.89
SW_B3: L2.1 U8.14 | length 148
  Bottom Layer w10: 468.84,689.09 478.16,698.4 U8.14@478.16,729.17
  Bottom Layer w15: 395.12,615.73 420.63,641.25 421,641.25 468.84,689.09
SYNCCLKIN: R75.2 U8.23 | length 109.7
  Bottom Layer w8.3: R75.2@358.93,916.56 360.24,915.26 390.08,915.26 414.56,890.78 455.83,890.78 U8.23@457.3,892.25
TCK: pad.37 U29.C12 | length 501.8
  Top Layer w10.6: U29.C12@1690.08,916.68 v2(1700.73,903.88)
  SIG2 w8.3: v2(1700.73,903.88) 1733.78,870.83 1736.21,868.4 1793.44,868.4 1806.78,881.74 2016,881.74 v2(2044.03,853.71)
  Bottom Layer w8.3: pad.37@1961.09,789.27 1979.59,789.27 2043.33,853.01 2043.33,853.71 v2(2044.03,853.71)
TDI: U29.D13 | length 16.6
  Top Layer w10.6: v2(1653.83,878.29) 1660.31,886.07 U29.D13@1664.49,891.09
TMS: U29.C14 | length 16.6
  Top Layer w10.6: v2(1677.28,876.15) 1685.06,869.67 U29.C14@1690.08,865.5
TRD1_N: L7.1 R265.2 | length 86.8
  Bottom Layer w8: R265.2@556.42,2331.03 585.06,2331.03 594.35,2340.32 L7.1@639.37,2340.32
TRD1_P: L7.2 R270.2 | length 88.5
  Bottom Layer w8: R270.2@557.24,2395.17 587.27,2395.17 602.75,2379.69 L7.2@639.37,2379.69
TRD2_N: C157.2 L7.4 | length 99.1
  Bottom Layer w8: L7.4@759.45,2340.32 793.64,2340.32 819.3,2314.65 C157.2@847.9,2314.65
TRD2_P: C161.2 L7.3 | length 98.1
  Bottom Layer w8: L7.3@759.45,2379.69 790.28,2379.69 813.54,2402.95 C161.2@847.9,2402.95
TRD3_N: C157.1 D15.1 PDB1.6 R281.2 | length 4183.3
  Top Layer w8: R281.2@915.64,2321.31 966.06,2321.31 974.55,2312.83 v2(1024,2312.83)
  SIG1 w8: v2(1024,2312.83) 1043.04,2312.83 1066.05,2335.84 1086.45,2335.84 1104.1,2318.2 1104.1,1635.21 ccw(c1117.6,1635.21) 1107.06,1626.76 1107.06,1626.65 1107.81,1625.9 1307.71,1426 1598.26,1426 1775.79,1248.46 2081.9,942.36 2629.97,942.36 2745.38,1057.77 2745.38,1518.01 2838.91,1611.54 3145.91,1611.54 3286.71,1470.73 3353.9,1470.73 PDB1.6@3396.36,1428.28
  Bottom Layer w8: C157.1@937.9,2314.65 939.71,2312.83 D15.1@996.49,2312.83 v2(1024,2312.83)
TRD3_P: C161.1 D17.1 PDB1.7 R275.2 | length 4202.8
  Top Layer w8: R275.2@915.64,2400.56 971.62,2400.56 978.41,2393.76 v2(1024,2393.76)
  SIG1 w8: v2(1024,2393.76) 1024.9,2392.86 1054.37,2392.86 1117.6,2329.64 1117.6,1635.21 1119.94,1632.86 1313.31,1439.5 1609.67,1439.5 2093.31,955.86 2619.04,955.86 2729.61,1066.42 2729.61,1524.26 2830.39,1625.04 3157.03,1625.04 3295.63,1486.45 3354.53,1486.45 PDB1.7@3396.36,1528.28
  Bottom Layer w8: C161.1@937.9,2402.95 948.54,2392.31 995.34,2392.31 D17.1@997.69,2394.66 998.14,2394.21 1023.55,2394.21 v2(1024,2393.76) ; D17.1@999.06,2401.32 D17.1@1002.55,2397.83
TX1: U29.B3 | length 1269.5
  Top Layer w8.4: U29.B3@1715.67,1146.99 1933.17,1146.99 ccw(c1933.17,1176.82) 1963,1176.82 1963,1223.01 cw(c1990.33,1223.01) 1990.33,1250.34 2040.33,1250.34 cw(c2040.33,1223.99) 2066.67,1223.99 2066.67,1185.52 ccw(c2104.87,1185.52) 2104.87,1147.32 2210.2,1147.32 ccw(c2210.2,1171.16) 2234.04,1171.16 2234.04,1300.7 ccw(c2203.86,1300.7) 2203.86,1330.87 2122.74,1330.87 cw(c2122.74,1537.96) 1915.65,1537.96
TX2: U29.B5 | length 1269.5
  Top Layer w8.4: U29.B5@1715.67,1095.81 2206.5,1095.81 ccw(c2206.5,1195.53) 2306.21,1195.53 2306.21,1312.29 ccw(c2219.62,1312.29) 2219.62,1398.88 2169.91,1398.88 cw(c2169.91,1498.88) 2069.91,1498.88 2069.91,1661.38
TX3: U29.B7 | length 1269.8
  Top Layer w8.4: U29.B7@1715.67,1044.63 2315.83,1044.63 ccw(c2315.83,1133.86) 2405.06,1133.86 2405.06,1389.96 ccw(c2338.96,1389.96) 2338.96,1456.06 2287.43,1456.06 cw(c2287.43,1519.29) 2224.2,1519.29 2224.2,1537.96
TX4: U29.B9 | length 1270.5
  Top Layer w8.4: U29.B9@1715.67,993.45 2320.54,993.45 ccw(c2320.54,1205.65) 2532.74,1205.65 2532.74,1537.96
VBGAP: C180.1 U29.K4 | length 43.8
  Top Layer w10.6: v2(1498.15,1110.75) 1505.92,1117.22 U29.K4@1510.94,1121.4
  Bottom Layer w15: v2(1498.15,1110.75) 1500.8,1108.09 C180.1@1524.24,1108.09
VPP_1P7: C150.2 P1.1 U29.U3 | length 1778.2
  Top Layer w4.19: 1259.19,1137.13 1262.14,1134.18 1300.91,1134.18 1318.99,1134.2 U29.U3@1331.81,1146.99
  Top Layer w15: C150.2@1203.29,1137.13 v2(1237.13,1137.13) 1259.19,1137.13
  SIG1 w20: v8(1316,1393.39) 1596,1393.39 1740.93,1248.46 1838.58,1150.81 2066.53,922.86 2337.82,922.86 P1.1@2415.78,844.9
  SIG2 w20: v2(1237.13,1137.13) 1237.13,1356.03 1274.63,1393.53 v8@1318.9,1393.53
VPP_EN: R159.1 U29.U8 | length 1534.6
  Top Layer w10.6: U29.U8@1331.81,1019.04 1336.83,1014.86 v2(1344.6,1008.38)
  SIG1 w5.5: v2(1344.6,1008.38) 1344.6,1007.42 1361.53,990.49 1378.9,990.49 1385.76,997.35 1407.18,997.35 1421.38,983.16 1421.38,940.19 1403.48,922.3 1403.48,833.91 1357.36,787.79 1357.36,707.43 1362.12,702.68 1420.75,644.04 2061,644.04 2082.49,622.55 2139.3,622.55 2246.43,729.68 2311.86,729.68 2350.32,691.22 v4(2350.32,689.93)
  SIG2 w5.5: v2@1343.98,1008.38 v2(1344.6,1008.38)
  Bottom Layer w8: R159.1@2350.32,658.05 v4(2350.32,689.93)
XREF_CLK0: U29.B13
XREF_CLK1: U29.D11 | length 16.6
  Top Layer w10.6: U29.D11@1664.49,942.27 1668.67,937.25 v2(1675.14,929.47)
XTALM: C108.1 U29.B1 Y3.3 | length 360.4
  Top Layer w6: U29.B1@1715.67,1198.17 1716.2,1198.17 1751.04,1233.01 1845.83,1233.01 1857.49,1244.68 1857.49,1275.4 1870.17,1288.08 1870.17,1333.18 1881.09,1344.1 1881.09,1395.51 1874.83,1401.77 1849.05,1401.77 Y3.3@1846.16,1398.88
XTALP: C106.1 U29.D1 Y3.1 | length 234.6
  Top Layer w6: U29.D1@1664.49,1198.17 1664.49,1199.35 1726.01,1260.87 1726.01,1284.25 C106.1@1729.95,1284.25 1730.28,1284.59 1730.28,1333.22 1752.64,1355.58 Y3.1@1791.04,1355.58
pads on no net: MAX-M8Q.4 MAX-M8Q.5 MAX-M8Q.15 MAX-M8Q.16 MAX-M8Q.17 MAX-M8Q.18 U5.11 U9. U15.17 U15.18 U15.19 U15.20 U27.4

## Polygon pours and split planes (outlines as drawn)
3V3_VIO on Top Layer "NONET_L-01_P-001" (solid, remove dead copper, pour order 1508): 943.19,705.15 1011.32,705.15 1041.33,675.14 1041.33,605.32 1028.47,592.47 987.4,592.47 943.25,636.61
1V2 on Top Layer "NONET_L-01_P-001" (solid, remove dead copper, pour order 1510): 30.48,445.71 149.79,445.71 149.79,310.03 148.69,308.93 30.27,308.93
1V0 on Top Layer "NONET_L-01_P-001" (solid, remove dead copper, pour order 1511): 30.27,1165.3 125.86,1165.3 139.69,1151.46 139.69,1001.66 30.88,1001.66 30.69,1001.47
1V8 on Top Layer "NONET_L-01_P-001" (solid, remove dead copper, pour order 1506): 819.21,1288.55 819.41,1288.76 878.71,1288.76 878.71,1164.59 878.93,1164.37 818.68,1164.37
REG3.3V on Top Layer "NONET_L-01_P-001" (solid, remove dead copper, pour order 1517): 2324.91,401.76 2359.44,428.52 2618.01,428.52 2618.01,155.06 2505.35,42.39 708.15,42.39 650.51,100.04 650.51,249.15 1972.09,249.15 1974.42,246.91 2297.21,246.36 2324.91,274.06
SW on Top Layer "NONET_L-01_P-001" (solid, remove dead copper, pour order 1513): 2443.82,664.06 2498.25,718.49 2790.61,718.49 2790.61,622.21 2775.15,606.75 2775.15,459.99 2377.37,459.99 2345.54,491.81 2345.54,626.78 2346.23,626.78 2383.51,664.06
12V_IN on Top Layer "NONET_L-01_P-001" (solid, remove dead copper, pour order 1516): 2936.34,771.2 3083.63,771.2 3100.64,788.21 3100.64,858.83 3041.14,918.33 3041.14,1029.75 3313.98,1029.75 3352.78,990.94 3352.78,875.57 3368.7,859.66 3368.7,734.02 3352.78,718.1 3352.78,634.36 3242.15,523.72 3070.24,523.72 3046.49,546.04 3046.49,701.35 3039.37,708.47 2936.34,708.31
NetCu6_1 on Top Layer "NONET_L-01_P-001" (solid, remove dead copper, pour order 1515): 3040.26,1428.28 3342.55,1428.28 3342.55,1084.43 3319.89,1061.78 3040.26,1061.78
ET_12V on Top Layer "NONET_L-01_P-001" (solid, remove dead copper, pour order 1514): 3157.96,1745.07 3468.1,1745.07 3468.1,1571.37 3352.78,1456.06 3054.45,1456.06 3054.45,1641.55
PMIN3V3 on Top Layer "Top Layer-REGOUT_3V3 2" (solid, pour order 1509): 480.5,592.47 480.5,413.23 403.3,413.23 403.3,592.47
PMIN3V3 on Top Layer "Top Layer-REGOUT_3V3 3" (solid, remove dead copper, pour order 1512): 605.7,946.87 619.7,960.87 619.89,1046.66 403.3,1046.66 403.3,973.75 430.17,946.87
AGND on Top Layer "AGND_L01_P1505" (solid, pour order 1505): 579.12,821 551.03,848.91 535.45,848.91 525.97,838.98 508.91,838.98 502.01,848.91 484.82,848.91 454.12,821 454.12,811.12 483.26,781.98 496.42,781.98 508.42,793.98 524.92,793.98 536.92,781.98 550.62,781.98 579.12,810.48
5V0 on Top Layer "Bottom Layer-5V0" (solid, remove dead copper, pour order 1507): 696.72,631.85 749.1,632.12 749.1,563.86 808.45,563.86 808.76,519.81 712.49,520.73 696.72,536.49
GND on Top Layer "Top Layer-GND 10" (solid, pour order 1498): 2079.52,1517.87 2079.52,1657.53 2107.62,1657.53 2107.62,1517.87
GND on Top Layer "Top Layer-GND 10" (solid, pour order 1499): 2028.81,1517.87 2028.81,1657.03 2059.24,1657.03 2059.24,1517.87
GND on Top Layer "NONET_L-01_P-001" (solid, remove dead copper, pour order 1518): 0.94,2557.45 5.05,2561.56 1042.08,2561.56 1042.08,1605.51 1124.73,1522.87 2857.53,1522.87 2857.53,2554.12 3544.79,2554.12 3544.79,0.01 0.01,0.01
1V2 on Top Layer "Top Layer-1V2" (solid, remove dead copper, pour order 1497): 1156.82,1045.22 1163.09,1045.22 1168.69,1050.82 1168.69,1093.21 1208.89,1093.21 1208.89,1014 1203.87,1008.98 1171.28,1008.98 1156.82,1023.44
1V8 on Top Layer "Top Layer-1V8" (solid, remove dead copper, pour order 1496): 1505.04,797.15 1490.04,782.15 1490.04,719.59 1508.97,700.65 1523.92,700.65 1526.53,703.26 1526.53,762.21 1519.47,769.28 1519.47,797.15
GND on Top Layer "Top Layer-GND 10" (solid, pour order 1501): 1682.2,1567.52 1682.2,2319.3 1690.08,2319.3 1690.08,1567.52
GND on Top Layer "Top Layer-GND 10" (solid, pour order 1502): 1607.4,1567.52 1607.4,2319.3 1615.27,2319.3 1615.27,1567.52
GND on Top Layer "Top Layer-GND 10" (solid, pour order 1504): 1532.6,1567.52 1532.6,2319.3 1540.47,2319.3 1540.47,1567.52
GND on Top Layer "Top Layer-GND 10" (solid, pour order 1500): 1457.79,1567.52 1457.79,2319.3 1465.67,2319.3 1465.67,1567.52
GND on Top Layer "Top Layer-GND 10" (solid, pour order 1503): 1382.99,1567.52 1382.99,2319.3 1390.86,2319.3 1390.86,1567.52
ET_12V on SIG1 "NONET_L-01_P-001" (solid, remove dead copper, pour order 1539): 3344.86,1699.4 3345.22,1699.77 3452.39,1699.77 3452.39,1595.83 3431.6,1575.04 3344.86,1575.05
AGND on SIG1 "AGND_L03_P1538" (solid, pour order 1538): 578.07,821.31 549.98,849.22 534.4,849.22 524.92,839.29 507.86,839.29 500.96,849.22 483.77,849.22 453.07,821.31 453.07,811.43 482.21,782.29 495.37,782.29 507.37,794.29 523.87,794.29 535.87,782.29 549.57,782.29 578.07,810.79
GND on SIG1 "SIG1-GND 1" (solid, pour order 1541): 0.01,0.01 3544.79,0.01 3544.79,2565.29 0.01,2565.29
GND on SIG1 "SIG1-GND" (solid, remove dead copper, pour order 1540): 1653.03,846.36 1684.38,815.01 1684.38,726.1 1675.45,717.18 1519.16,717.18 1446.97,789.37 1446.97,826.38 1466.94,846.36
ET_12V on SIG2 "NONET_L-01_P-001" (solid, remove dead copper, pour order 1543): 3346.1,1700.69 3346.46,1701.06 3453.63,1701.06 3453.63,1597.12 3432.84,1576.33 3346.1,1576.33
AGND on SIG2 "AGND_L06_P1542" (solid, pour order 1542): 578.35,819.05 550.26,846.96 534.68,846.96 525.2,837.03 508.14,837.03 501.24,846.96 484.05,846.96 453.35,819.05 453.35,809.17 482.49,780.03 495.65,780.03 507.65,792.03 524.15,792.03 536.15,780.03 549.85,780.03 578.35,808.53
GND on SIG2 "GND_L06_P1545" (solid, pour order 1545): 0.01,0.01 3544.79,0.01 3544.79,2565.29 0.01,2565.29
1V2 on SIG2 "SIG2-1V2" (solid, remove dead copper, pour order 1544): 1167.38,1163.24 1241.77,1237.63 1565.87,1237.63 1659.05,1144.45 1659.05,920.13 1659.05,889.29 1510.44,740.68 1336.87,740.68 1235.72,841.82 1235.72,940.09 1212.74,940.09 1168.79,983.31
ET_12V on Bottom Layer "NONET_L-01_P-001" (solid, remove dead copper, pour order 1559): 3350.75,1694.04 3351.12,1694.41 3458.28,1694.41 3458.28,1590.47 3437.49,1569.69 3350.75,1569.69
3V3_VIO on Bottom Layer "NONET_L-01_P-001" (solid, remove dead copper, pour order 1565): 832,707.86 852.07,727.94 995.51,727.94 1031.19,692.26 1031.19,638.42 1002.96,610.2 849.64,610.58 832,628.21
12V_IN on Bottom Layer "NONET_L-01_P-001" (solid, remove dead copper, pour order 1571): 3105.14,903.09 3303.42,903.09 3303.42,739.53 3105.14,739.53
3V3_VIO on Bottom Layer "NONET_L-01_P-001" (solid, remove dead copper, pour order 1564): 2186.23,413.53 2186.23,552.39 2171.9,566.72 2095.16,566.72 2076.89,548.45 2076.89,413.53
PMIN3V3 on Bottom Layer "Bottom Layer-REGOUT_3V3 1" (solid, pour order 1556): 496.51,1007.86 490.55,1013.82 490.5,1092.62 431.76,1092.62 431.76,1008.52 487.98,952.31 487.98,939.1 487.98,866.85 502.67,866.85 502.67,963.54 496.51,969.7
PMICOUT_1V8 on Bottom Layer "Bottom Layer-PMICOUT_1V8" (solid, remove dead copper, pour order 1570): 844.22,1062.06 844.22,1110.07 790.49,1110.07 624.85,1110.07 624.85,1008.66 706.9,1008.66 767.62,947.94 874.1,947.94 883.06,956.89 883.06,1017.53 844.22,1056.36
REG3.3V on Bottom Layer "NONET_L-01_P-001" (solid, remove dead copper, pour order 1574): 553.86,386.93 756.47,386.77 887.19,256.05 2567.57,256.05 2567.57,40.98 602.34,40.98 553.86,89.47
PMIN3V3 on Bottom Layer "Bottom Layer-REGOUT_3V3 3" (solid, pour order 1573): 505.6,400.37 536.13,369.84 536.13,115.39 392.82,115.39 392.82,336.56 409.97,353.72 409.97,577.4 478.47,645.9 502.31,646.1 502.31,609.1 486.75,593.53 486.75,491.09 505.6,472.24
1V0 on Bottom Layer "Bottom Layer-1V0_FILTERED" (solid, pour order 1572): -13.31,1175.54 169.61,1175.54 169.61,983.03 17.07,983.03 -13.31,1013.4
1V2 on Bottom Layer "Bottom Layer-1V2" (solid, remove dead copper, pour order 1568): 132.94,537.03 94.85,575.12 69.17,575.12 14.22,575.12 14.22,336.04 132.94,336.04
PMICOUT_1V2 on Bottom Layer "Bottom Layer-PMICOUT_1V2" (solid, remove dead copper, pour order 1569): 205.67,418.6 252.81,465.74 396.76,465.74 396.76,569.98 145.25,570 145.25,418.6
PMICOUT_1V0 on Bottom Layer "Bottom Layer-PMICOUT_1V0" (solid, remove dead copper, pour order 1566): 190.82,1113.17 181.23,1113.17 181.23,977.27 263.54,977.27 314.75,1028.49 408.17,1028.49 408.17,1113.17
+3.3VD on Bottom Layer "NONET_L-01_P-001" (solid, remove dead copper, pour order 1562): 717.55,748.19 724.63,741.11 792.79,741.11 810.01,723.89 810.01,653.53 694.47,653.53 674.25,673.75 641.86,706.13 603.8,706.13 603.8,748.19
PMIN3V3 on Bottom Layer "Bottom Layer-REGOUT_3V3" (solid, pour order 1555): 537.85,1011.27 544.21,1017.63 544.21,1094.84 600.51,1094.84 600.51,1008.71 546.34,954.54 546.34,869.07 531.65,869.07 531.65,965.76 537.81,971.93
SW_B3 on Bottom Layer "Bottom Layer-SW1" (solid, remove dead copper, pour order 1554): 317.79,629.95 393.48,629.95 470.62,707.09 470.62,723.72 473.15,726.26 485.41,726.26 485.41,675.24 394.61,584.45 317.79,584.45
PMIN3V3 on Bottom Layer "Bottom Layer-REGOUT_3V3 2" (solid, pour order 1553): 581.13,502.85 593.46,490.52 691.08,490.52 691.08,532.57 656.52,567.13 581.13,567.13
5V0 on Bottom Layer "Bottom Layer-5V0" (solid, remove dead copper, pour order 1563): 810.34,609.55 781.93,637.95 692.9,637.95 651.06,679.8 636.24,664.98 663.27,637.95 663.27,572.91 706.26,529.92 810.34,529.92
SW_B2 on Bottom Layer "Bottom Layer-SW2" (solid, remove dead copper, pour order 1552): 390.08,953.62 345.43,953.62 336.19,966.52 336.19,1005.5 406.58,1005.5 483.54,928.55 483.54,875.35 470.27,875.35 470.27,909.13 470.27,928.02 460.85,937.43 406.28,937.43
AGND on Bottom Layer "AGND_L08_P1551" (solid, pour order 1551): 579.8,816.81 551.71,844.72 536.13,844.72 526.65,834.79 509.59,834.79 502.69,844.72 485.5,844.72 454.8,816.81 454.8,806.93 483.94,777.79 497.1,777.79 509.1,789.79 525.6,789.79 537.6,777.79 551.3,777.79 579.8,806.29
SW_B1 on Bottom Layer "Bottom Layer-SW3" (solid, remove dead copper, pour order 1550): 564.67,924.53 575.73,924.53 598.92,947.72 692.22,947.72 692.22,991.52 606.66,991.52 564.67,950.12
NetL1_1 on Bottom Layer "Bottom Layer-NetL1_1" (solid, remove dead copper, pour order 1549): 577.06,656.88 637.13,656.88 647.91,646.1 647.91,598.6 577.06,598.6
GND on Bottom Layer "NONET_L-01_P-001" (solid, remove dead copper, pour order 1575): 0.01,2556.24 3544.79,2556.24 3544.79,0.01 5.14,0.01
3V3 on Bottom Layer "NONET_L-01_P-001" (solid, remove dead copper, pour order 1560): 1950.85,598.05 2037.16,598.05 2057.05,578.15 2057.05,475.36 2039.24,457.55 1950.06,457.55
1V0 on Bottom Layer "Bottom Layer-1V0_RF1 1" (solid, remove dead copper, pour order 1557): 1504.39,1127.72 1487.63,1110.96 1436.18,1110.96 1436.18,1141.65 1462.23,1141.65 1475.04,1154.47 1475.04,1201.22 1588.26,1201.22 1588.26,1127.72
1V8 on Bottom Layer "Bottom Layer-1V8 1" (solid, remove dead copper, pour order 1558): 1423.52,1260.55 1423.52,1316.67 1498.15,1316.67 1498.15,1278.85 1462.82,1243.74 1462.82,1184.7 1443.94,1184.7 1432.92,1173.67 1389.73,1173.67 1384.99,1168.93 1345.7,1168.93 1345.7,1221.66 1358.01,1233.97 1395.79,1233.97 1395.79,1260.55
1V0 on Bottom Layer "Bottom Layer-1V0_RF2" (solid, remove dead copper, pour order 1561): 1627.48,1103.56 1661.19,1103.56 1669,1095.75 1802.74,1095.75 1802.74,1011.31 1627.48,1011.31
1V8 on Bottom Layer "Bottom Layer-1V8_FILTERED" (solid, remove dead copper, pour order 1567): 767.62,1294.12 767.62,1139.84 781.15,1126.31 839.53,1126.31 920.17,1126.31 920.17,1270.33 896.38,1294.12
ET_12V on PWR1 "NONET_L-01_P-001" (solid, remove dead copper, pour order 1522): 3342.31,1700.44 3342.68,1700.8 3449.84,1700.8 3449.84,1596.87 3429.05,1576.08 3342.31,1576.08
3V3_VIO on PWR1 "NONET_L-01_P-001" (solid, remove dead copper, pour order 1521): 828.08,1432.13 900.25,1432.13 900.25,1321.59 887.69,1309.04 828.08,1309.04
3V3_VIO on PWR1 "NONET_L-01_P-001" (solid, remove dead copper, pour order 1523): 937.53,730.67 1051.49,730.67 1051.49,613.01 1052.66,611.85 935,611.85
5V0 on PWR1 "NONET_L-01_P-001" (solid, remove dead copper, pour order 1519): 747.71,564.45 805.12,564.45 821.52,548.05 821.52,480.62 758.76,480.62 747.71,491.67
AGND on PWR1 "AGND_L04_P1520" (solid, pour order 1520): 580.93,817.03 552.83,844.94 537.26,844.94 527.77,835 510.72,835 503.81,844.93 486.62,844.93 455.93,817.03 455.93,807.14 485.07,778 498.22,778 510.22,790 526.72,790 538.72,778 552.42,778 580.93,806.51
1V0 on PWR1 "PWR1-1V0_RF1" (solid, remove dead copper, pour order 1525): 24.66,1309.04 504.76,1789.13 1101.91,1789.13 1220.77,1670.26 1436.77,1670.26 1792.56,1341.44 1792.56,1021.08 1735.5,1021.08 1662.8,1021.08 1662.8,1081.99 1697.8,1116.98 1697.8,1150.14 1669.04,1178.9 1532.64,1178.9 1476.38,1122.64 1436.77,1122.64 1436.77,1188.86 1452.19,1204.28 1452.19,1305.45 1309.15,1448.49 1190.01,1448.49 1134.19,1392.67 1134.19,1244.66 1017.83,1244.66 943.03,1319.46 943.03,1496.81 890.52,1549.32 596.89,1549.32 251.97,1204.4 251.97,1061.78 195.77,1005.59 53.16,1005.59 24.66,1034.08
GND on PWR1 "PWR1-GND" (solid, pour order 1526): 0.01,0.01 3544.79,0.01 3544.79,2565.29 0.01,2565.29
3V3 on PWR1 "PWR2-3V3" (solid, remove dead copper, pour order 1524): 1677.55,703.3 1686.1,711.85 1685.3,755.69 1737.08,807.46 1737.08,898.5 1855.59,898.5 2072.38,681.71 2072.38,523.42 1902.3,523.42 1831.1,594.61 1142.69,594.61 1142.69,767.59 1262.32,887.22 1262.32,1031.83 1315.99,1031.83 1326.74,1021.08 1326.74,832.5 1241.45,747.21 1241.45,708.34 1262.33,687.46 1330.52,687.46 1354.04,710.98 1354.04,750.36 1390.69,750.36 1437.75,703.3
ET_12V on PWR2 "NONET_L-01_P-001" (solid, remove dead copper, pour order 1530): 3344.86,1705.29 3345.22,1705.66 3452.39,1705.66 3452.39,1601.72 3431.6,1580.94 3344.86,1580.94
1V8 on PWR2 "PWR2-1V8" (solid, remove dead copper, pour order 1532): 1479.77,746.93 1665.03,746.93 1677.39,759.29 1677.39,953.56 1661.06,969.89 1661.06,991.65 1702,1032.59 1701.39,1133.06 1684.83,1146.44 1667.71,1146.44 1663.2,1141.93 1663.2,1125.72 1655.93,1119.48 1635.47,1119.48 1603.61,1151.34 819.17,1151.34 819.36,1279.48 844.14,1304.27 1260.09,1304.27 1287.36,1279.48 1801.56,1279.48 1857.88,1223.16 1857.88,601.18 1346.03,601.18 1303.73,643.48 1303.73,746.93
3V3_VIO on PWR2 "NONET_L-01_P-001" (solid, remove dead copper, pour order 1529): 2190.41,392.13 2190.41,475 2173.33,492.07 2093.69,492.07 2074.18,472.56 2074.18,392.13
3V3_VIO on PWR2 "NONET_L-01_P-001" (solid, remove dead copper, pour order 1528): 821.16,1347.57 821.81,1348.23 821.81,1435.14 833.16,1446.48 888.15,1446.48 888.15,1348.1 889.16,1347.09
1V2 on PWR2 "PWR1-1V2" (solid, remove dead copper, pour order 1533): 1041.56,764.11 1646.42,764.11 1646.42,916.13 1437.82,916.13 1437.82,1083.01 892.87,1083.01 714.88,905.03 714.88,516.76 657.07,458.95 329.34,458.95 179.5,608.78 14.67,608.78 14.67,398.26 188.5,224.43 716.43,224.43 952.72,460.72 952.72,676.74
PMIN3V3 on PWR2 "NONET_L-01_P-001" (solid, remove dead copper, pour order 1531): 439.25,1082.05 612.92,1082.05 703.32,991.65 703.32,524.7 654.19,475.57 519.52,475.57 486.27,442.32 390.9,442.32 279.58,553.63 279.58,912.7
AGND on PWR2 "AGND_L05_P1527" (solid, pour order 1527): 576.96,820.09 552.68,844.21 533.29,844.21 523.8,834.27 506.75,834.27 499.85,844.21 482.66,844.21 451.96,816.3 451.96,806.41 481.1,777.27 494.25,777.27 506.25,789.27 522.75,789.27 534.75,777.27 548.45,777.27 576.96,805.78
GND on PWR2 "GND_L05_P1534" (solid, pour order 1534): 0.01,0.01 3544.79,0.01 3544.79,2565.29 0.01,2565.29
no net on Top Solder "Top Solder-No Net" (solid, pour order 1576): 1451.67,1187.62 1467.85,1187.62 1467.85,1214.32 1502.8,1214.32 1502.8,1187.62 1519.08,1187.62 1519.08,1214.32 1553.98,1214.32 1553.98,1187.62 1570.26,1187.62 1570.26,1214.32 1605.26,1214.32 1605.26,1187.62 1621.59,1187.62 1621.59,1215.48 1671.18,1265.07 1671.18,1308.94 1686.14,1323.9 1686.14,1493.77 1836.71,1493.77 1923.98,1406.5 1923.98,1245.66 1860.49,1182.18 1833.55,1182.18 1828.49,1177.12 1757.91,1177.12 1757.91,1155.03 1732.1,1155.03 1732.1,1138.85 1757.9,1138.85 1757.9,1103.91 1732.1,1103.91 1732.1,1087.67 1757.9,1087.67 1757.9,1052.77 1732.1,1052.77 1732.1,1036.49 1757.9,1036.49 1757.91,1001.59 1732.1,1001.59 1732.1,985.31 1757.91,985.31 1757.91,967.87 2621.32,967.87 2621.32,2552.33 1318.67,2552.33 1318.67,1415.59 1395.79,1415.59 1395.79,1303.44 1437,1262.23 1437,1214.32 1451.67,1214.32
ET_12V on GND2 "NONET_L-01_P-001" (solid, remove dead copper, pour order 1547): 3346.1,1704.8 3346.46,1705.17 3453.63,1705.17 3453.63,1601.23 3432.84,1580.44 3346.1,1580.44
AGND on GND2 "AGND_L07_P1546" (solid, pour order 1546): 579.74,819.04 551.65,846.95 536.07,846.95 526.59,837.02 509.53,837.02 502.63,846.95 485.44,846.95 454.74,819.04 454.74,809.16 483.88,780.02 497.04,780.02 509.04,792.02 525.54,792.02 537.54,780.02 551.24,780.02 579.74,808.52
GND on GND2 "GND_L07_P1548" (solid, pour order 1548): 0.01,0.01 3544.79,0.01 3544.79,2565.29 0.01,2565.29
ET_12V on GND1 "NONET_L-01_P-001" (solid, remove dead copper, pour order 1536): 3346.7,1700.44 3347.06,1700.8 3454.23,1700.8 3454.23,1596.87 3433.44,1576.08 3346.7,1576.08
AGND on GND1 "AGND_L02_P1535" (solid, pour order 1535): 578.38,820.38 550.28,848.29 534.71,848.29 525.22,838.35 508.17,838.35 501.26,848.29 484.08,848.29 453.38,820.38 453.38,810.49 482.52,781.35 495.67,781.35 507.67,793.35 524.17,793.35 536.17,781.35 549.87,781.35 578.38,809.86
GND on GND1 "GND_L02_P1537" (solid, remove dead copper, pour order 1537): 0.01,0.01 3544.79,0.01 3544.79,2565.29 0.01,2565.29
